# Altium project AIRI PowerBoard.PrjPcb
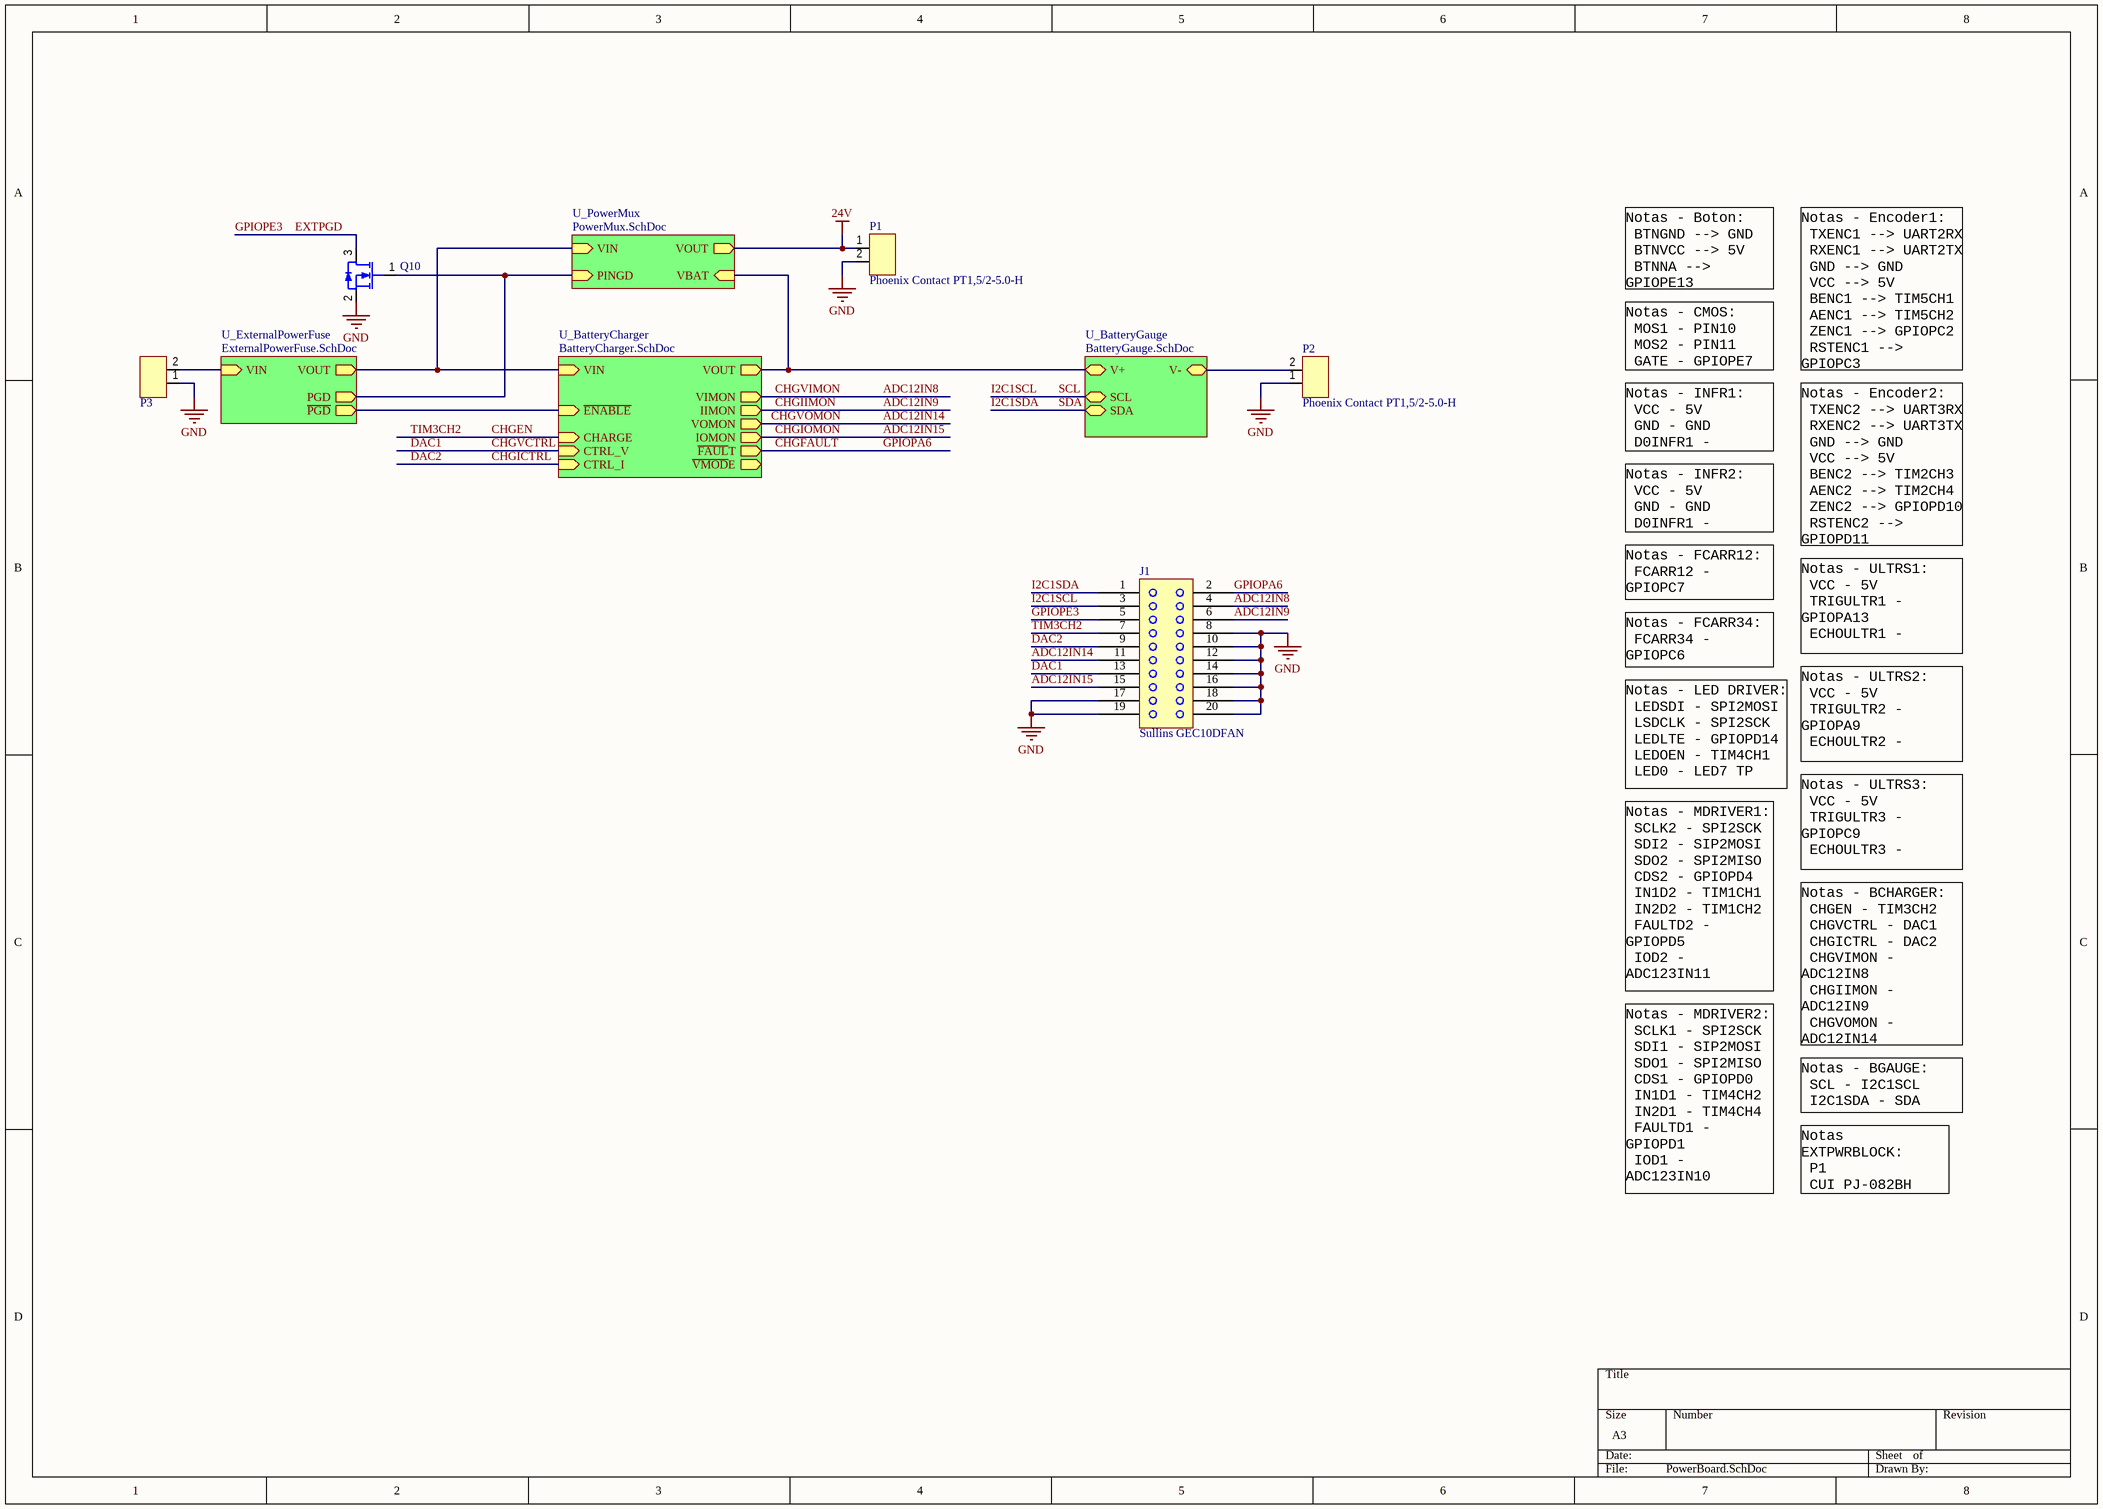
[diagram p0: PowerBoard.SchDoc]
5 sheets, 86 parts. Net scope: hierarchical (ports join the sheet entries above them; power ports are global).
Sheets:
  PowerBoard.SchDoc
    U_ExternalPowerFuse = ExternalPowerFuse.SchDoc
    U_BatteryCharger = BatteryCharger.SchDoc
    U_BatteryGauge = BatteryGauge.SchDoc
    U_PowerMux = PowerMux.SchDoc

## Sheet PowerBoard.SchDoc
size A3; DocumentNumber: 1; SheetNumber: 1; SheetTotal: 9

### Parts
J1  Sullins GEC10DFAN  [PCB-68ly7omgfaejvkbwbwsx-1]
P1  Phoenix Contact PT1,5/2-5.0-H  [PCB-uxxh2nr7ib8r5ep0eqej-1]
P2  Phoenix Contact PT1,5/2-5.0-H  [PCB-uxxh2nr7ib8r5ep0eqej-1]
P3  Phoenix Contact PT1,5/2-5.0-H  [PCB-uxxh2nr7ib8r5ep0eqej-1]  (value not drawn)
Q10  ON Semiconductor NTR5103NT1G  [PCB-4trtqjanqmpdw865ivvf-1]  (value not drawn)

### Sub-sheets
U_BatteryCharger = BatteryCharger.SchDoc: ~{FAUL}T (out), ~{VMOD}E (out), ~{ENABLE} (in), CTRL_V (in), VOUT, VIN (in), CHARGE (in), CTRL_I (in), VOMON (out), IIMON (out), VIMON (out), IOMON (out)
U_BatteryGauge = BatteryGauge.SchDoc: V- (bidir), V+ (bidir), SDA (bidir), SCL (bidir)
U_ExternalPowerFuse = ExternalPowerFuse.SchDoc: PGD (out), ~{PGD} (out), VOUT (out), VIN (in)
U_PowerMux = PowerMux.SchDoc: VIN (in), VBAT (in), VOUT (out), PINGD (in)

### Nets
24V: P1.1 ; sheet U_PowerMux/VOUT
GND: J1.8 J1.10 J1.12 J1.14 J1.16 J1.17 J1.18 J1.19 J1.20 P1.2 P2.1 P3.1 Q10.2(S)
ADC12IN8: J1.4 ; sheet U_BatteryCharger/VIMON  [also labelled CHGVIMON]
ADC12IN9: J1.6 ; sheet U_BatteryCharger/IIMON  [also labelled CHGI~{I}MON]
ADC12IN14: J1.11 ; sheet U_BatteryCharger/VOMON  [also labelled CHGVOMON]
ADC12IN15: J1.15 ; sheet U_BatteryCharger/IOMON  [also labelled CHGIOMON]
~{CHGFAULT}: J1.2 ; sheet U_BatteryCharger/~{FAUL}T  [also labelled GPIOPA6]
CHGEN: J1.7 ; sheet U_BatteryCharger/CHARGE  [also labelled TIM3CH2]
CHGICTRL: J1.9 ; sheet U_BatteryCharger/CTRL_I  [also labelled DAC2]
CHGVCTRL: J1.13 ; sheet U_BatteryCharger/CTRL_V  [also labelled DAC1]
EXTPGD: J1.5 Q10.3(D)  [also labelled GPIOPE3]
I2C1SCL: J1.3 ; sheet U_BatteryGauge/SCL  [also labelled SCL]
I2C1SDA: J1.1 ; sheet U_BatteryGauge/SDA  [also labelled SDA]
VIN: sheet U_ExternalPowerFuse/VOUT, sheet U_BatteryCharger/VIN, sheet U_PowerMux/VIN
NetC14_2: P2.2 ; sheet U_BatteryGauge/V-
NetC15_1: P3.2 ; sheet U_ExternalPowerFuse/VIN
NetC18_1: sheet U_BatteryCharger/VOUT, sheet U_BatteryGauge/V+, sheet U_PowerMux/VBAT
NetQ2_1: sheet U_ExternalPowerFuse/~{PGD}, sheet U_BatteryCharger/~{ENABLE}
NetQ9_1: Q10.1(G) ; sheet U_ExternalPowerFuse/PGD, sheet U_PowerMux/PINGD

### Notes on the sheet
- Notas - Boton:
  BTNGND --> GND
  BTNVCC --> 5V
  BTNNA --> GPIOPE13
  BTNCMN --> 3.3V
- Notas - CMOS:
  MOS1 - PIN10
  MOS2 - PIN11
  GATE - GPIOPE7
- Notas - Encoder1:
  TXENC1 --> UART2RX
  RXENC1 --> UART2TX
  GND --> GND
  VCC --> 5V
  BENC1 --> TIM5CH1
  AENC1 --> TIM5CH2
  ZENC1 --> GPIOPC2
  RSTENC1 --> GPIOPC3
- Notas - INFR1:
  VCC - 5V
  GND - GND
  D0INFR1 - GPIOPA15
- Notas - INFR2:
  VCC - 5V
  GND - GND
  D0INFR1 - GPIOPA14
- Notas - Encoder2:
  TXENC2 --> UART3RX
  RXENC2 --> UART3TX
  GND --> GND
  VCC --> 5V
  BENC2 --> TIM2CH3
  AENC2 --> TIM2CH4
  ZENC2 --> GPIOPD10
  RSTENC2 --> GPIOPD11
- Notas - FCARR12:
  FCARR12 - GPIOPC7
  GND - GND
- Notas - ULTRS1:
  VCC - 5V
  TRIGULTR1 - GPIOPA13
  ECHOULTR1 - GPIOPA10
  GND - GND
- Notas - FCARR34:
  FCARR34 - GPIOPC6
  GND - GND
- Notas - LED DRIVER:
  LEDSDI - SPI2MOSI
  LSDCLK - SPI2SCK
  LEDLTE - GPIOPD14
  LEDOEN - TIM4CH1
  LED0 - LED7 TP
- Notas - ULTRS2:
  VCC - 5V
  TRIGULTR2 - GPIOPA9
  ECHOULTR2 - GPIOPA8
  GND - GND
- Notas - ULTRS3:
  VCC - 5V
  TRIGULTR3 - GPIOPC9
  ECHOULTR3 - GPIOPC8
  GND - GND
- Notas - MDRIVER1:
  SCLK2 - SPI2SCK
  SDI2 - SIP2MOSI
  SDO2 - SPI2MISO
  CDS2 - GPIOPD4
  IN1D2 - TIM1CH1
  IN2D2 - TIM1CH2
  FAULTD2 - GPIOPD5
  IOD2 - ADC123IN11
  SLPD2 - GPIOPD6
  DISD2 - GPIOPD7
- Notas - BCHARGER:
  CHGEN - TIM3CH2
  CHGVCTRL - DAC1
  CHGICTRL - DAC2
  CHGVIMON - ADC12IN8
  CHGIIMON - ADC12IN9
  CHGVOMON - ADC12IN14
  CHGIOMON - ADC12IN15
  CHGFAULT - GPIOPA6
- Notas - BGAUGE:
  SCL - I2C1SCL
  I2C1SDA - SDA
- Notas - MDRIVER2:
  SCLK1 - SPI2SCK
  SDI1 - SIP2MOSI
  SDO1 - SPI2MISO
  CDS1 - GPIOPD0
  IN1D1 - TIM4CH2
  IN2D1 - TIM4CH4
  FAULTD1 - GPIOPD1
  IOD1 - ADC123IN10
  SLPD1 - GPIOPD2
  DISD1 - GPIOPD3
- Notas EXTPWRBLOCK:
  P1
  CUI PJ-082BH

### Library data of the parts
J1 = CMP-0579cccb4b8ddabe-1: Conn Header Vert 20POS 2.54MM
P1-P3 = CMP-29d3e01a948df614-2: TERM BLK, PCB, SCREW, 5.0MM, 2WAY; Connector Type: Terminal Block, PCB; Series: PT 1.5; Connector Mounting: PCB; Pitc...
Q10 = CMP-02f4c92c4c09dd33-6: Small Signal MOSFET 60V 310mA 2.5mOhm Single N-Channel SOT-23 Small Signal MOSFET

## Sheet ExternalPowerFuse.SchDoc
size A; DocumentNumber: 5; SheetNumber: 5; SheetTotal: 9
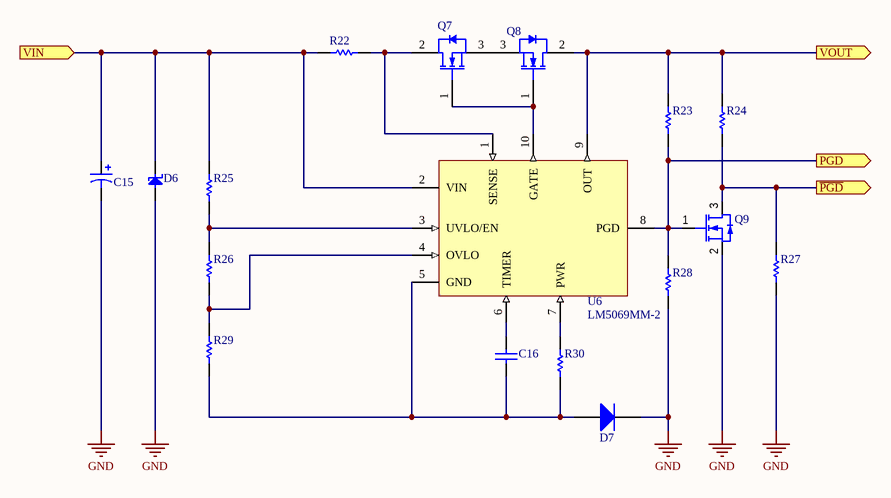
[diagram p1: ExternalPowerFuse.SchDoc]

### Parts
C15  Panasonic EEE-HA1V101XP  [PCB-yncmx9jt7av7ibwhpkx7-1]  (value not drawn)
C16  Murata GRM21BR71C475KE51L  [PCB-w2q6b3n3rziootmrv9wz-1]  (value not drawn)
D6  SMBJ28A  [PCB-c143qqmc0v6vbhfo61i0-1]  (value not drawn)
D7  1N4148  [SODFL250X100-2M]  (value not drawn)
Q7  IPB042N10N3 G  [HTD2PAK]  (value not drawn)
Q8  IPB042N10N3 G  [HTD2PAK]  (value not drawn)
Q9  ON Semiconductor NTR5103NT1G  [PCB-4trtqjanqmpdw865ivvf-1]  (value not drawn)
R22  Yageo PA2512FKF070R003E  [PCB-y7eyzpmf577hs4y1ib8m-1]  (value not drawn)
R23  Royal Ohm 0805S8J0104T5E  [PCB-74rwo1kpr8i4opkqrny0-1]  (value not drawn)
R24  Royal Ohm 0805S8J0104T5E  [PCB-74rwo1kpr8i4opkqrny0-1]  (value not drawn)
R25  Yageo RC0805FR-0712KL  [PCB-rf5zg00kfirz45jag8tm-1]  (value not drawn)
R26  Yageo RC0805FR-073K9L  [RC0805FR]  (value not drawn)
R27  Royal Ohm 0805S8J0104T5E  [PCB-74rwo1kpr8i4opkqrny0-1]  (value not drawn)
R28  Royal Ohm 0805S8J0104T5E  [PCB-74rwo1kpr8i4opkqrny0-1]  (value not drawn)
R29  Yageo RC0805FR-071K5L  [RESC2013X60X35ML10T20]  (value not drawn)
R30  Yageo RC0805FR-0715KL  [RC0805FR]  (value not drawn)
U6  LM5069MM-2  [MUB10A_L]

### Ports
PGD (out), VIN (in), VOUT (out), ~{PGD} (out)

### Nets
GND: C15.2 D6.2(A) D7.2(K) Q9.2(S) R27.1 R28.1
VIN: Q8.2(DRAIN) R23.2 R24.2 U6.9(OUT) ; port VOUT
NetC15_1: C15.1 D6.1(K) R22.1 R25.2 U6.2(VIN) ; port VIN
NetC16_1: C16.1 D7.1(A) R29.1 R30.1 U6.5(GND)
NetC16_2: C16.2 U6.6(TIMER)
NetQ2_1: Q9.3(D) R24.1 R27.2 ; port ~{PGD}
NetQ7_1: Q7.1(GATE) Q8.1(GATE) U6.10(GATE)
NetQ7_2: Q7.2(DRAIN) R22.2 U6.1(SENSE)
NetQ7_3: Q7.3(SOURCE) Q8.3(SOURCE)
NetQ9_1: Q9.1(G) R23.1 R28.2 U6.8(PGD) ; port PGD
NetR25_1: R25.1 R26.2 U6.3(UVLO/EN)
NetR26_1: R26.1 R29.2 U6.4(OVLO)
NetR30_2: R30.2 U6.7(PWR)

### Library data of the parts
C15 = CMP-2d6fe63f67daf2a8-1: Electrolytic capacitor SMD 100 µF 35 V 20 % (Ø) 6.3 mm Panasonic EEE-HA1V101XP 1 pc(s); Lead-Free Status: Lead Free
C16 = CMP-1004dbd64457cfc3-1: Cap Ceramic 4.7uF 16V X7R 10% SMD 0805 125°C Embossed Plastic T/R; Capacitance: 4.70 µF; Case/Package (SI): 2012; Voltage Rating (DC): 16.0 V
D6 = CMP-ea40234f95603587-2: Transient Voltage Suppressor, TVS, SMBJ Series, Unidirectional, 28 V, DO-214AA, 2, 31.1 V; Operating Voltage: 28.0 V; Power Rating: 600 W
D7 = CMP-814637-10: Small Signal Diode, 75 V, 0.15 A, -55 to 150 degC, 2-Pin SOD-323, RoHS, Tape and Reel
Q7 Q8 = CMP-4154385-7: N-Channel OptiMOS 3 Power-Transistor, 100 V VDS, 100 A ID, -55 to 175 degC, PG-TO-263-3-2, Reel, Green
Q9 = CMP-02f4c92c4c09dd33-6: as Q10 on sheet PowerBoard
R22 = CMP-e7152d208e6b38d2-1: Res Current Sense Metal Film 2512 3m Ohms 1% 1W ±100ppm/°C Molded SMD Emboss T/R; Lead-Free Status: Lead Free
R23 R24 R27 R28 = CMP-c86102680bbe17a6-1: 0805 100000±5% SMD Resistor
R25 = CMP-c51b0e735db01adc-1: Surface Mount Thick Film Resistor, RC Series, 12 kohm, 125 mW, - 1%, 150 V, 0805 [2012 Metric]; Power Rating: 125 mW; Resistance: 12.0 kΩ; Lead-Free Status: Lead Free; Voltage Rating (DC): 150 V; Case/Package (SI): 2012
R26 = CMP-7439bf43b49eabfe-2: Res Thick Film 0805 3.9K Ohm 1% 0.125W(1/8W) ±100ppm/C Pad SMD T/R; Case/Package (SI): 2012; Lead-Free Status: Lead Free; Power Rating: 125 mW; Resistance: 3.90 k?; Temperature Coefficient: -100 ppm/°C to 100 ppm/°C; Voltage Rating (DC): 150 V
R29 = CMP-d3c9198dcc7e0c0e-3: RC Series 0805 0.125 W 1.5 kOhms 1% ±100 ppm/°C SMT Thick Film Chip Resistor; Voltage Rating (DC): 150.0 V; Case/Package (SI): 2012; Resistance: 1500.0 Ω; Power Rating: 0.125 W; Lead-Free Status: Lead Free
R30 = CMP-7c99b7f1295ea35e-4: Res Thick Film 0805 15K Ohm 1% 0.125W(1/8W) ±100ppm/C Pad SMD T/R; Case/Package (SI): 2012; Lead-Free Status: Lead Free; Power Rating: 125 mW; Resistance: 15.0 k?; Temperature Coefficient: -100 ppm/°C to 100 ppm/°C; Voltage Rating (DC): 150 V
U6 = CMP-0063-01367-4: Positive High Voltage Hot Swap / Inrush Current Controller with Power Limiting, 10-pin MSOP; Input Voltage (DC): 80.0 V; Lead-Free Status: Contains Lead; Number of Outputs: 1; Output Voltage: 12.0 V

## Sheet BatteryCharger.SchDoc
size A; DocumentNumber: 2; SheetNumber: 2; SheetTotal: 9
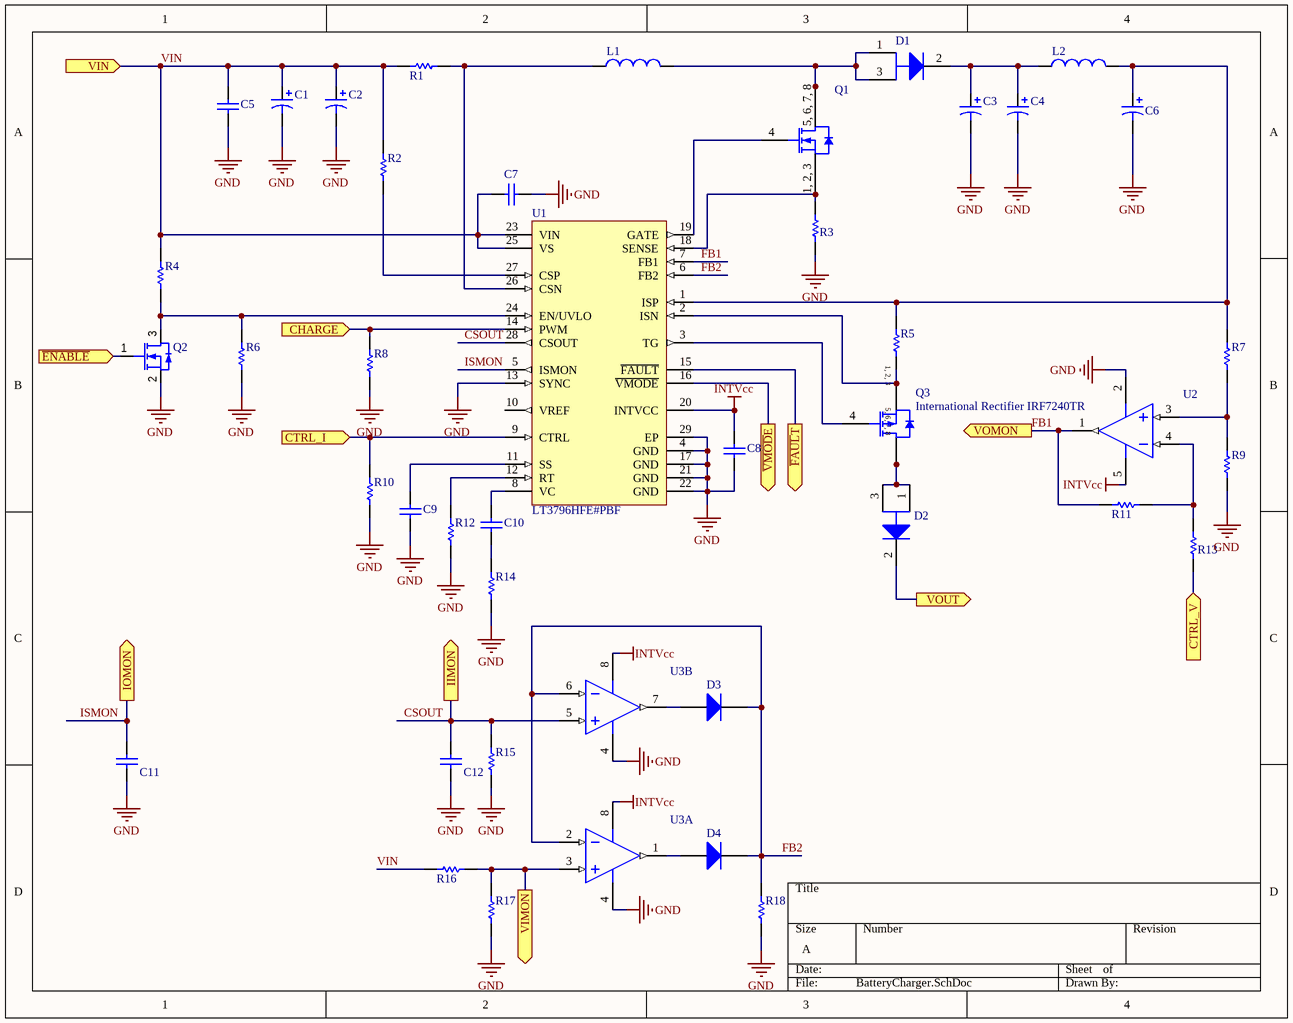
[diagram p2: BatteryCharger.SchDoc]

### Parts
(Parts that share a designator on the sheet are numbered #1, #2 ... from top to bottom, then left to right.)
C1  Nichicon UCZ1V102MNQ1MS  [PCB-bcbaik4jkplkhzapcvdz-1]  (value not drawn)
C2  Nichicon UCZ1V102MNQ1MS  [PCB-bcbaik4jkplkhzapcvdz-1]  (value not drawn)
C3  Panasonic EEE-TP1V242V  [PCB-hvlu7flpkoii6dt3whhj-1]  (value not drawn)
C4  Panasonic EEE-TP1V242V  [PCB-hvlu7flpkoii6dt3whhj-1]  (value not drawn)
C5  Murata GRM21BC8YA106ME11L  [PCB-l65gribcpxdbehxrnx9m-1]  (value not drawn)
C6  Panasonic EEH-ZK1V331P  [Panasonic Series ZK Type V Size G]  (value not drawn)
C7  GCM21BR71H224KA37L  [PCB-vg7sak9ne95jdn7rrir5-1]  (value not drawn)
C8  Murata GRM21BR71C475KE51L  [PCB-w2q6b3n3rziootmrv9wz-1]  (value not drawn)
C9  Murata GCD21BR71H104KA01L  [PCB-ssva2zk340p4bh5zvq6f-1]  (value not drawn)
C10  GCM21BR71H224KA37L  [PCB-vg7sak9ne95jdn7rrir5-1]  (value not drawn)
C11  Murata GCD21BR71H104KA01L  [PCB-ssva2zk340p4bh5zvq6f-1]  (value not drawn)
C12  Murata GCD21BR71H104KA01L  [PCB-ssva2zk340p4bh5zvq6f-1]  (value not drawn)
D1  MBRB1645T4G  [HTD2PAK]  (value not drawn)
D2  MBRB1645T4G  [HTD2PAK]  (value not drawn)
D3  1N4148  [SODFL250X100-2M]  (value not drawn)
D4  1N4148  [SODFL250X100-2M]  (value not drawn)
L1  74437529203680  [WE-HCF-2920-ROUND]  (value not drawn)
L2  ECS International ECS-MPIL0630-R82MC  [PCB-ggb9vcl7y0791unwiq1o-1]  (value not drawn)
Q1  Infineon IRF7470TRPBF  [SOIC8]  (value not drawn)
Q2  ON Semiconductor NTR5103NT1G  [PCB-4trtqjanqmpdw865ivvf-1]  (value not drawn)
Q3  International Rectifier IRF7240TR  [PCB-9asxttw8ky8znwucor51-1]
R1  Yageo PE2512FKE070R008L  [PCB-y7eyzpmf577hs4y1ib8m-1]  (value not drawn)
R2  Yageo RC0805FR-072K1L  [PCB-8aw9ivy9cn5fb1kp6023-1]  (value not drawn)
R3  Yageo PE2512FKE070R008L  [PCB-y7eyzpmf577hs4y1ib8m-1]  (value not drawn)
R4  Yageo RC0805FR-0734KL  [RESC2013X60X35ML10T20]  (value not drawn)
R5  Yageo RL2512FK-070R075L  [PCB-3v9gat8leddio7l68v0s-1]  (value not drawn)
R6  Yageo RC0805FR-075K6L  [RC0805FR]  (value not drawn)
R7  Yageo RC0805FR-07100KL  [RESC2013X60X35ML10T20]  (value not drawn)
R8  Royal Ohm 0805S8J0104T5E  [PCB-74rwo1kpr8i4opkqrny0-1]  (value not drawn)
R9  Yageo RC0805FR-072K1L  [PCB-8aw9ivy9cn5fb1kp6023-1]  (value not drawn)
R10  Royal Ohm 0805S8J0104T5E  [PCB-74rwo1kpr8i4opkqrny0-1]  (value not drawn)
R11  Yageo RC0805FR-0727KL  [PCB-6ihbot7fpvk2duhebx6y-1]  (value not drawn)
R12  Yageo RC0805FR-0719K6L  [PCB-bzdswkldtwwbfmx064vx-1]  (value not drawn)
R13  Yageo RC0805FR-0727KL  [PCB-6ihbot7fpvk2duhebx6y-1]  (value not drawn)
R14  RC0805FR-071K8L  [PCB-bvxj1do1ymnvdak8omsp-1]  (value not drawn)
R15  Yageo RC0805FR-0733KL  [PCB-a6w3ttwem4kxlulsflmi-1]  (value not drawn)
R16  Yageo RC0805FR-0727KL  [PCB-6ihbot7fpvk2duhebx6y-1]  (value not drawn)
R17  RC0805FR-071K8L  [PCB-bvxj1do1ymnvdak8omsp-1]  (value not drawn)
R18  Royal Ohm 0805S8J0104T5E  [PCB-74rwo1kpr8i4opkqrny0-1]  (value not drawn)
U1  LT3796HFE#PBF  [LT-FE-28-EPV-EB_N]
U2  Diodes Inc. TLV271CW5-7  [SOP-5]  (value not drawn)
U3#1  Diodes Inc. TLV272CS-13  [SO8]  (value not drawn)  (part B of 2)
U3#2  Diodes Inc. TLV272CS-13  [SO8]  (value not drawn)  (part A of 2)

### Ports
CHARGE (in), CTRL_I (in), CTRL_V (in), IIMON (out), IOMON (out), VIMON (out), VIN (in), VOMON (out), VOUT (out), ~{ENABLE} (in), ~{FAUL}T (out), ~{VMOD}E (out)

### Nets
GND: C1.2 C2.2 C3.2 C4.2 C5.2 C6.2 C7.2 C8.1 C9.1 C11.1 C12.1 Q2.2(S) R3.1 R6.1 R8.1 R9.1 R10.1 R12.1 R14.1 R15.2 R17.1 R18.1 U1.4(GND) U1.13(SYNC) U1.17(GND) U1.21(GND) U1.22(GND) U1.29(EP) U2.2(GND) U3#1.4(GND) U3#2.4(GND)
INTVcc: C8.2 U1.20(INTVCC) U2.5(VDD) U3#1.8(VDD) U3#2.8(VDD)
ADC12IN8: R16.1 R17.2 U3#2.3(IN1+) ; port VIMON
~{CHGFAULT}: U1.15(~{FAULT}) ; port ~{FAUL}T
CHGEN: R8.2 U1.14(PWM) ; port CHARGE
CHGICTRL: R10.2 U1.9(CTRL) ; port CTRL_I
CHGVCTRL: R13.2 ; port CTRL_V
CSOUT: C12.2 R15.1 U1.28(CSOUT) U3#1.5(IN2+) ; port IIMON  [project net ADC12IN9]
FB1: R11.2 U1.7(FB1) U2.1(OUT) ; port VOMON  [project net ADC12IN14]
FB2: D3.2(K) D4.2(K) R18.2 U1.6(FB2) U3#1.6(IN2-) U3#2.2(IN1-)
ISMON: C11.2 U1.5(ISMON) ; port IOMON  [project net ADC12IN15]
VIN: C1.1 C2.1 C5.1 C7.1 R1.2 R2.2 R4.2 R16.2 U1.23(VIN) U1.25(VS) ; port VIN
NetC3_1: C3.1 C4.1 D1.2(K) L2.1
NetC6_1: C6.1 L2.2 R5.2 R7.2 U1.1(ISP)
NetC9_2: C9.2 U1.11(SS)
NetC10_1: C10.1 R14.2
NetC10_2: C10.2 U1.8(VC)
NetC18_1: D2.2(K) ; port VOUT
NetD1_1: D1.1(A) D1.3(A) L1.2 Q1.5(D) Q1.6(D) Q1.7(D) Q1.8(D)
NetD2_1: D2.1(A) D2.3(A) Q3.5(D) Q3.6(D) Q3.7(D) Q3.8(D)
NetD3_1: D3.1(A) U3#1.7(OUT2)
NetD4_1: D4.1(A) U3#2.1(OUT1)
NetL1_1: L1.1 R1.1 U1.26(CSN)
NetQ1_1: Q1.1(S) Q1.2(S) Q1.3(S) R3.2 U1.18(SENSE)
NetQ1_4: Q1.4(G) U1.19(GATE)
NetQ2_1: Q2.1(G) ; port ~{ENABLE}
NetQ2_3: Q2.3(D) R4.1 R6.2 U1.24(EN/UVLO)
NetQ3_1: Q3.1(S) Q3.2(S) Q3.3(S) R5.1 U1.2(ISN)
NetQ3_4: Q3.4(G) U1.3(TG)
NetR2_1: R2.1 U1.27(CSP)
NetR7_1: R7.1 R9.2 U2.3(IN+)
NetR11_1: R11.1 R13.1 U2.4(IN-)
NetR12_2: R12.2 U1.12(RT)
NetU1_16: U1.16(~{VMODE}) ; port ~{VMOD}E

Not connected (* = marked no-connect by the designer): U1 10(VREF)

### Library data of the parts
C1 C2 = CMP-b1e57bdc431a6e22-1: Cap Aluminum 1000uF 35V 20% (16 X 16.5mm) SMD Cylindrical 0.047 Ohm 2400mA 3500hr 125°C T/R
C3 C4 = CMP-cde80182784c122f-1: Cap Aluminum Lytic 2400uF 35V 20%( 18 X 21.5mm) SMD 0.032 Ohm 3250mA 4000h 125C Automotive T/R; Capacitance: 2.40 mF; Equivalent Series Resistance (ESR): 32.0 m?; Voltage Rating (DC): 35.0 V
C5 = CMP-762ebc35716ba9e9-1: 0805 10 uF 35 V ±20% Tolerance X6S Multilayer Ceramic Capacitor; Capacitance: 10.0 µF; Lead-Free Status: Lead Free; Voltage Rating (DC): 35.0 V
C6 = CMP-bfb3722bbd176074-3: EEH ZK (V) Series 35 V 330 uF 105°C 10x10.2 mm SMT Hybrid Aluminum Polymer
C7 C10 = CMP-120835-3: Multilayer Ceramic Capacitor, Aec-Q200 Gcm Series, 0.22 F, 10%, X7R, 50 V Rohs Compliant: Yes
C8 = CMP-1004dbd64457cfc3-1: as C16 on sheet ExternalPowerFuse
C9 C11 C12 = CMP-5b5d9311dba3849a-1: Cap Ceramic 0.1uF 50V X7R 10% Pad SMD 0805 125C Automotive T/R; Capacitance: 100 nF; Voltage Rating (DC): 50.0 V
D1 D2 = CMP-822676-10: SWITCHMODE(TM) Power Rectifier, 45 V, 3-Pin D2PAK, Pb-Free, Tube
D3 D4 = CMP-814637-10: as D7 on sheet ExternalPowerFuse
L1 = CMP-513d9d7ae6d18efa-2: WE-HCF High Current Inductor
L2 = CMP-81f64dc1435b5e31-1: Inductor Power Shielded Wirewound 0.82uH 20% 100KHz Iron 14A 0.006Ohm DCR T/R
Q1 = CMP-983352d49b9a47f4-3: Mosfet, Power; N-ch; Vdss 40V; Rds(on) 9 Milliohms; Id 10A; SO-8; Pd 2.5W; Vgs +/-12V; Drain to Source Voltage (Vds): 40.0 V; Current Rating: 11.0 A; Rise Time: 1.90 ns; Power Dissipation: 2.50 W; Continuous Drain Current (Ids): 11.0 A, 10.0 A; Drain to Source Resistance (on) (Rds): 9.00 mΩ; Polarity: N-Channel
Q2 = CMP-02f4c92c4c09dd33-6: as Q10 on sheet PowerBoard
Q3 = CMP-7c61b56e738ca3a6-1: -40V Single P-Channel HEXFET Power MOSFET in a SO-8 package; Current Rating: -10.5 A; Continuous Drain Current (Ids): 10.5 A; Lead-Free Status: Contains Lead; Power Dissipation: 2.50 W (max); Rise Time: 490 ns; Drain to Source Voltage (Vds): 40.0 V; Voltage Rating (DC): -40.0 V
R1 R3 = CMP-f6aa3cc66161296d-1: Res Metal Foil 2512 0.008 Ohm 1% 1W ±50ppm/C Epoxy SMD Automotive T/R; Resistance: 8.00 mΩ
R2 R9 = CMP-eedc2589d763311b-2: RC Series 0805 0.125 W 2.1 kOhms 1% ±100 ppm/°C SMT Thick Film Chip Resistor; Power Rating: 125 mW; Lead-Free Status: Lead Free; Case/Package (SI): 2012
R4 = CMP-1854680-2: RES SMD 34K OHM 1% 1/8W 0805; Case/Package (SI): 2012; Lead-Free Status: Lead Free; Power Rating: 0.125 W; Resistance: 34000.0 Ω; Voltage Rating (DC): 150.0 V
R5 = CMP-40798806d0629fbe-1: Res Thick Film 2512 0.075 Ohm 1% 1W ±800ppm/C Pad SMD Automotive T/R; Lead-Free Status: Lead Free; Resistance: 75.0 m?
R6 = CMP-5c9997e7c49d835e-2: Res Thick Film 0805 5.6K Ohm 1% 0.125W(1/8W) ±100ppm/C Pad SMD T/R; Power Rating: 125 mW; Case/Package (SI): 2012; Voltage Rating (DC): 150 V; Resistance: 5.60 k?; Temperature Coefficient: -100 ppm/°C to 100 ppm/°C; Lead-Free Status: Lead Free
R7 = CMP-1854318-18: Res Thick Film 0805 100K Ohm 1% 0.125W(1/8W} 100ppm/Molded SMD Paper T/R
R8 R10 R18 = CMP-c86102680bbe17a6-1: 0805 100000±5% SMD Resistor
R11 R13 R16 = CMP-843b4f6e63345bfc-1: Res Thick Film 0805 27K Ohm 1% 0.125W(1/8W) ±100ppm/C Pad SMD T/R; Case/Package (SI): 2012; Lead-Free Status: Lead Free; Power Rating: 125 mW; Resistance: 27.0 k?; Temperature Coefficient: -250 ppm/°C to 250 ppm/°C; Voltage Rating (DC): 150 V
R12 = CMP-70d9bbb3619aaf1e-1: Res Thick Film 0805 19.6K Ohm 1% 1/8W ?100ppm/C Molded SMD SMD Paper T/R; Case/Package (SI): 2012; Lead-Free Status: Lead Free; Power Rating: 125 mW; Resistance: 19.6 k?; Temperature Coefficient: -100 ppm/°C to 100 ppm/°C; Voltage Rating (DC): 150 V
R14 R17 = CMP-5911926b99ed86d6-2: Res Thick Film 0805 1.8K Ohm 1% 0.125W(1/8W) ±100ppm/C Pad SMD T/R; Power Rating: 125 mW; Voltage Rating (DC): 150 V; Lead-Free Status: Lead Free; Resistance: 1.80 kΩ
R15 = CMP-e4eb2f957d343b2c-2: Res Thick Film 2.0 x 1.2 mm 33K Ohm 1% 0.125W(1/8W) 100ppm/ C Molded SMD Paper T/R; Lead-Free Status: Lead Free; Resistance: 33.0 kΩ; Case/Package (SI): 2012; Voltage Rating (DC): 150 V
U1 = CMP-1228589-2: Constant-Current and Constant-Voltage Controller with Dual Current Sense, 6 to 100 V Vin, 100 V Vout MAX, 28-pin SOP (FE-28-EPV-EB), -40 to 150 degC, Pb-Free; Lead-Free Status: Lead Free; Output Current: 10.0 A
U2 = CMP-0d49c6506e26d28e-1: TLV271 Series 16 V 1.9 MHz CMOS Rail to Rail Output Operational Amplifier-SOT-25; Lead-Free Status: Lead Free
U3#1 U3#2 = CMP-b6657db9f9c269a2-1: Op Amp Dual GP R-R O/P ±8V/16V 8-Pin SO T/R

## Sheet BatteryGauge.SchDoc
size A; DocumentNumber: 7; SheetNumber: 7; SheetTotal: 9
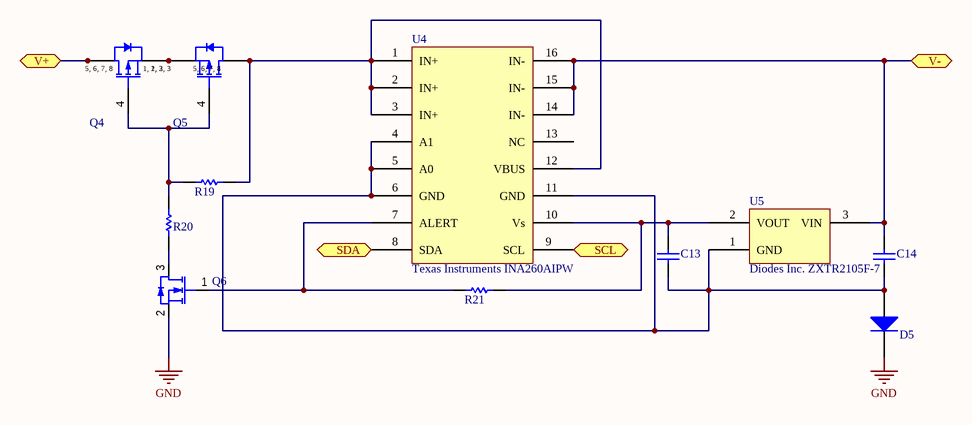
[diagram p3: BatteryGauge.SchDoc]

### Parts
C13  GRM21BR71C475KE51L  [PCB-w2q6b3n3rziootmrv9wz-1]  (value not drawn)
C14  Murata GCM21BR71H105KA03L  [C0805]  (value not drawn)
D5  1N4148  [SODFL250X100-2M]  (value not drawn)
Q4  International Rectifier IRF7240TR  [PCB-9asxttw8ky8znwucor51-1]  (value not drawn)
Q5  International Rectifier IRF7240TR  [PCB-9asxttw8ky8znwucor51-1]  (value not drawn)
Q6  ON Semiconductor NTR5103NT1G  [PCB-4trtqjanqmpdw865ivvf-1]  (value not drawn)
R19  Royal Ohm 0805S8J0104T5E  [PCB-74rwo1kpr8i4opkqrny0-1]  (value not drawn)
R20  Royal Ohm 0805S8J0104T5E  [PCB-74rwo1kpr8i4opkqrny0-1]  (value not drawn)
R21  Royal Ohm 0805S8J0104T5E  [PCB-74rwo1kpr8i4opkqrny0-1]  (value not drawn)
U4  Texas Instruments INA260AIPW  [PCBComponent_1]
U5  Diodes Inc. ZXTR2105F-7  [PCB-e2zlw08ew8gq5kp16zvm-1]

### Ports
SCL (bidir), SDA (bidir), V+ (bidir), V- (bidir)

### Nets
GND: D5.2(K) Q6.2(S)
I2C1SCL: U4.9(SCL) ; port SCL
I2C1SDA: U4.8(SDA) ; port SDA
NetC13_1: C13.1 C14.1 D5.1(A) U4.4(A1) U4.5(A0) U4.6(GND) U4.11(GND) U5.1(GND)
NetC13_2: C13.2 R21.1 U4.10(Vs) U5.2(VOUT)
NetC14_2: C14.2 U4.14(IN-) U4.15(IN-) U4.16(IN-) U5.3(VIN) ; port V-
NetC18_1: Q4.5(D) Q4.6(D) Q4.7(D) Q4.8(D) ; port V+
NetQ4_1: Q4.1(S) Q4.2(S) Q4.3(S) Q5.1(S) Q5.2(S) Q5.3(S)
NetQ4_4: Q4.4(G) Q5.4(G) R19.2 R20.1
NetQ5_5: Q5.5(D) Q5.6(D) Q5.7(D) Q5.8(D) R19.1 U4.1(IN+) U4.2(IN+) U4.3(IN+) U4.12(VBUS)
NetQ6_1: Q6.1(G) R21.2 U4.7(ALERT)
NetQ6_3: Q6.3(D) R20.2

Not connected (* = marked no-connect by the designer): U4 13(NC)

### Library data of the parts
C13 = CMP-1004dbd64457cfc3-1: Cap Ceramic 4.7uF 16V X7R 10% SMD 0805 125°C Embossed Plastic T/R; Voltage Rating (DC): 16.0 V
C14 = CMP-9133247-3: Cap Ceramic 1uF 50V X7R 10% SMD 0805 125C Embossed T/R; Voltage Rating (DC): 50.0 V; Lead-Free Status: Lead Free
D5 = CMP-814637-10: as D7 on sheet ExternalPowerFuse
Q4 Q5 = CMP-7c61b56e738ca3a6-1: as Q3 on sheet BatteryCharger
Q6 = CMP-02f4c92c4c09dd33-6: as Q10 on sheet PowerBoard
R19-R21 = CMP-c86102680bbe17a6-1: 0805 100000±5% SMD Resistor
U4 = CMP-a7ab6adaf6cd786c-5: High/Low-Side Digital Current/Power Monitor with Integrated 2mΩ Shunt Resistor 16-TSSOP -40 to 125
U5 = CMP-92df589abaf04d18-2: LDO Regulator Pos 5V 0.03A Automotive 3-Pin SOT-23 T/R; Lead-Free Status: Lead Free

## Sheet PowerMux.SchDoc
size A; DocumentNumber: 6; SheetNumber: 6; SheetTotal: 9
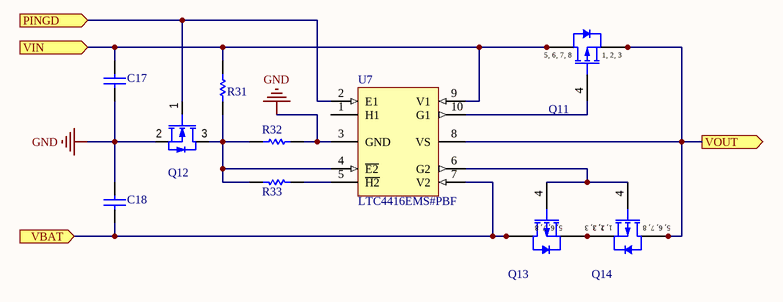
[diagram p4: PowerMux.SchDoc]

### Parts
C17  Murata GCM21BR71H105KA03L  [C0805]  (value not drawn)
C18  Murata GCM21BR71H105KA03L  [C0805]  (value not drawn)
Q11  International Rectifier IRF7240TR  [PCB-9asxttw8ky8znwucor51-1]  (value not drawn)
Q12  ON Semiconductor NTR5103NT1G  [PCB-4trtqjanqmpdw865ivvf-1]  (value not drawn)
Q13  International Rectifier IRF7240TR  [PCB-9asxttw8ky8znwucor51-1]  (value not drawn)
Q14  International Rectifier IRF7240TR  [PCB-9asxttw8ky8znwucor51-1]  (value not drawn)
R31  Yageo RC0805FR-0727KL  [PCB-6ihbot7fpvk2duhebx6y-1]  (value not drawn)
R32  Yageo RC0805FR-074K7L  [RESC2013X60X35ML10T20]  (value not drawn)
R33  Yageo RC0805FR-07130KL  [RC0805FR]  (value not drawn)
U7  LTC4416EMS#PBF  [LT-MS-10_L]

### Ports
PINGD (in), VBAT (in), VIN (in), VOUT (out)

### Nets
24V: Q11.1(S) Q11.2(S) Q11.3(S) Q14.5(D) Q14.6(D) Q14.7(D) Q14.8(D) U7.8(VS) ; port VOUT
GND: C17.1 C18.2 Q12.2(S) R32.2 U7.3(GND)
VIN: C17.2 Q11.5(D) Q11.6(D) Q11.7(D) Q11.8(D) R31.1 U7.9(V1) ; port VIN
NetC18_1: C18.1 Q13.5(D) Q13.6(D) Q13.7(D) Q13.8(D) U7.7(V2) ; port VBAT
NetQ9_1: Q12.1(G) U7.2(E1) ; port PINGD
NetQ11_4: Q11.4(G) U7.10(G1)
NetQ12_3: Q12.3(D) R31.2 R32.1 R33.1 U7.4(~{E2})
NetQ13_1: Q13.1(S) Q13.2(S) Q13.3(S) Q14.1(S) Q14.2(S) Q14.3(S)
NetQ13_4: Q13.4(G) Q14.4(G) U7.6(G2)
NetR33_2: R33.2 U7.5(~{H2})

Not connected (* = marked no-connect by the designer): U7 1(H1)

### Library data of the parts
C17 C18 = CMP-9133247-3: as C14 on sheet BatteryGauge
Q11 Q13 Q14 = CMP-7c61b56e738ca3a6-1: as Q3 on sheet BatteryCharger
Q12 = CMP-02f4c92c4c09dd33-6: as Q10 on sheet PowerBoard
R31 = CMP-843b4f6e63345bfc-1: as R11 on sheet BatteryCharger
R32 = CMP-3926451-6: Res Thick Film 0805 4.7K Ohm 1% 0.125W(1/8W) ?100ppm/C Molded SMD Paper T/R; Lead-Free Status: Lead Free; Case/Package (SI): 2012
R33 = CMP-f2153b0d72f32dd2-5: Res Thick Film 0805 130K Ohm 1% 0.125W(1/8W) ±100ppm/C Pad SMD T/R; Case/Package (SI): 2012; Lead-Free Status: Lead Free; Power Rating: 125 mW; Resistance: 130 k?; Temperature Coefficient: -100 ppm/°C to 100 ppm/°C; Voltage Rating (DC): 150 V
U7 = CMP-1435175-3: Low Loss Dual PowerPath Controller for Large PFET, 3.6 to 36 V Vin, 10-pin SOP (MS-10), -40 to 85 degC, Pb-Free

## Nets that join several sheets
24V: PowerBoard (P1.1), PowerMux (8 pins)
GND: PowerBoard (13 pins), ExternalPowerFuse (6 pins), BatteryCharger (31 pins), BatteryGauge (D5.2 Q6.2), PowerMux (5 pins)
ADC12IN8: PowerBoard (J1.4), BatteryCharger (R16.1 R17.2 U3#2.3)
ADC12IN9: PowerBoard (J1.6), BatteryCharger (C12.2 R15.1 U1.28 U3#1.5)
ADC12IN14: PowerBoard (J1.11), BatteryCharger (R11.2 U1.7 U2.1)
ADC12IN15: PowerBoard (J1.15), BatteryCharger (C11.2 U1.5)
~{CHGFAULT}: PowerBoard (J1.2), BatteryCharger (U1.15)
CHGEN: PowerBoard (J1.7), BatteryCharger (R8.2 U1.14)
CHGICTRL: PowerBoard (J1.9), BatteryCharger (R10.2 U1.9)
CHGVCTRL: PowerBoard (J1.13), BatteryCharger (R13.2)
I2C1SCL: PowerBoard (J1.3), BatteryGauge (U4.9)
I2C1SDA: PowerBoard (J1.1), BatteryGauge (U4.8)
NetC14_2: PowerBoard (P2.2), BatteryGauge (5 pins)
NetC15_1: PowerBoard (P3.2), ExternalPowerFuse (5 pins)
NetC18_1: BatteryCharger (D2.2), BatteryGauge (Q4.5 Q4.6 Q4.7 Q4.8), PowerMux (6 pins)
NetQ2_1: ExternalPowerFuse (Q9.3 R24.1 R27.2), BatteryCharger (Q2.1)
NetQ9_1: PowerBoard (Q10.1), ExternalPowerFuse (Q9.1 R23.1 R28.2 U6.8), PowerMux (Q12.1 U7.2)
VIN: ExternalPowerFuse (Q8.2 R23.2 R24.2 U6.9), BatteryCharger (10 pins), PowerMux (7 pins)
